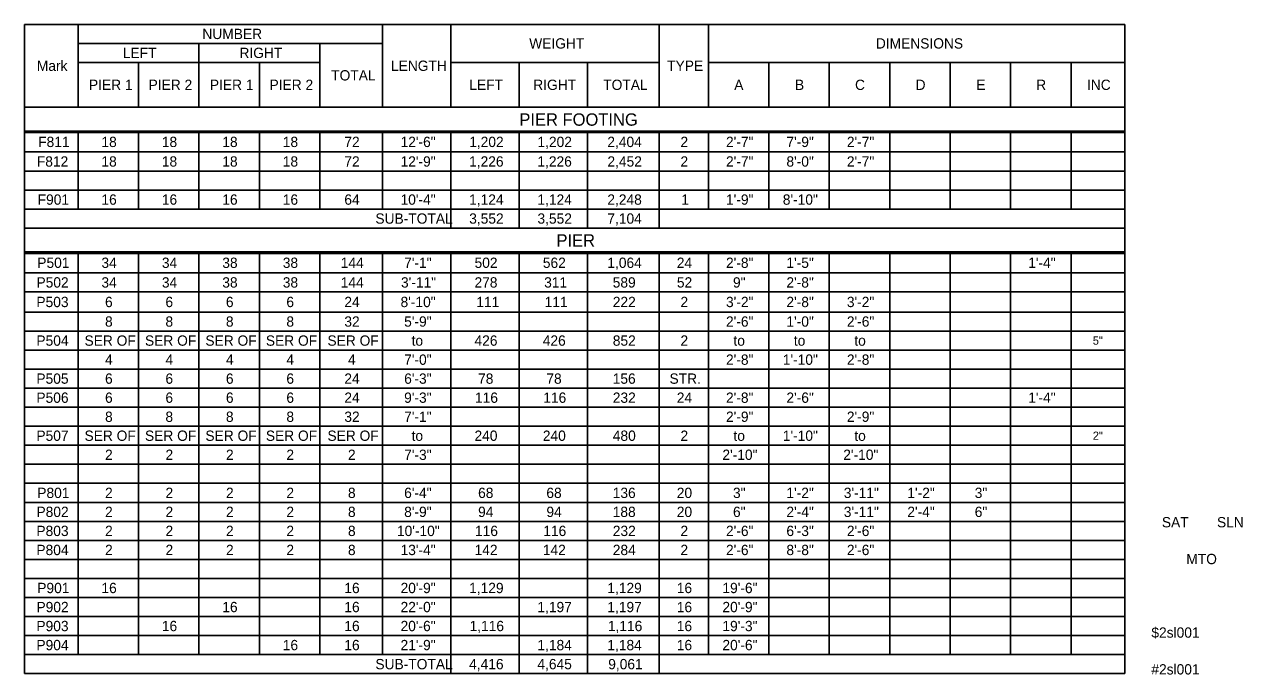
# Model space of a CAD drawing. Extents: x -18.5 to 33.3, y 0.6 to 37.5.
# Drawn here: x 16.73 to 33.29, y 0.6 to 9.44 of the extents above; entities that cross this region are included whole.
import ezdxf

# ---------------------------------------------------------------- set-up
doc = ezdxf.new("R2010")
doc.units = 0
for name, color, linetype in [('BR_X_Beam_Centerline', 7, 'Continuous'), ('BR_X_Beam_Object', 7, 'Continuous'), ('Default', 7, 'Continuous')]:
    doc.layers.add(name, color=color, linetype=linetype)

msp = doc.modelspace()

# ---------------------------------------------------------------- linework, layer by layer
at = {"layer": 'Default'}
for p, q in [((16.731, 9.443), (31.689, 9.443)), ((16.731, 9.443), (16.731, 7.972)), ((17.462, 9.443), (17.462, 8.317)), ((21.601, 9.443), (21.601, 8.317)), ((22.529, 9.443), (22.529, 8.317)), ((25.359, 9.443), (25.359, 8.317)), ((26.029, 9.443), (26.029, 8.317)), ((31.689, 9.443), (31.689, 7.972)), ((17.462, 9.184), (21.601, 9.184)), ((19.105, 9.184), (19.105, 8.317)), ((20.749, 9.184), (20.749, 8.317)), ((17.462, 8.925), (20.749, 8.925)), ((18.283, 8.925), (18.283, 8.317)), ((19.927, 8.925), (19.927, 8.317)), ((22.529, 8.925), (25.359, 8.925)), ((23.457, 8.925), (23.457, 8.317)), ((24.385, 8.925), (24.385, 8.317)), ((26.029, 8.925), (31.689, 8.925)), ((26.85, 8.925), (26.85, 8.317)), ((27.672, 8.925), (27.672, 8.317)), ((28.494, 8.925), (28.494, 8.317)), ((29.316, 8.925), (29.316, 8.317)), ((30.137, 8.925), (30.137, 8.317)), ((30.959, 8.925), (30.959, 8.317)), ((16.731, 8.317), (31.689, 8.317)), ((16.731, 7.992), (31.689, 7.992)), ((16.731, 7.992), (16.731, 6.328)), ((16.731, 7.972), (31.689, 7.972)), ((17.462, 7.972), (17.462, 6.932)), ((18.283, 7.972), (18.283, 6.932)), ((19.105, 7.972), (19.105, 6.932)), ((19.927, 7.972), (19.927, 6.932)), ((20.749, 7.992), (20.749, 6.932)), ((21.601, 7.972), (21.601, 6.932)), ((22.529, 7.972), (22.529, 6.673)), ((23.457, 7.972), (23.457, 6.673)), ((24.385, 7.992), (24.385, 6.673)), ((25.359, 7.972), (25.359, 6.673)), ((26.029, 7.972), (26.029, 6.932)), ((26.85, 7.972), (26.85, 6.932)), ((27.672, 7.972), (27.672, 6.932)), ((28.494, 7.972), (28.494, 6.932)), ((29.316, 7.972), (29.316, 6.932)), ((30.137, 7.972), (30.137, 6.932)), ((30.959, 7.972), (30.959, 6.932)), ((31.689, 7.992), (31.689, 6.328)), ((16.731, 7.708), (31.689, 7.708)), ((16.731, 7.449), (31.689, 7.449)), ((16.731, 7.191), (31.689, 7.191)), ((16.731, 6.932), (31.689, 6.932)), ((16.731, 6.673), (31.689, 6.673)), ((16.731, 6.349), (31.689, 6.349)), ((16.731, 6.349), (16.731, 0.617)), ((16.731, 6.328), (31.689, 6.328)), ((17.462, 6.328), (17.462, 0.876)), ((18.283, 6.328), (18.283, 0.876)), ((19.105, 6.328), (19.105, 0.876)), ((19.927, 6.328), (19.927, 0.876)), ((20.749, 6.349), (20.749, 0.876)), ((21.601, 6.328), (21.601, 0.876)), ((22.529, 6.328), (22.529, 0.617)), ((23.457, 6.328), (23.457, 0.617)), ((24.385, 6.349), (24.385, 0.617)), ((25.359, 6.328), (25.359, 0.617)), ((26.029, 6.328), (26.029, 0.876)), ((26.85, 6.328), (26.85, 0.876)), ((27.672, 6.328), (27.672, 0.876)), ((28.494, 6.328), (28.494, 0.876)), ((29.316, 6.328), (29.316, 0.876)), ((30.137, 6.328), (30.137, 0.876)), ((30.959, 6.328), (30.959, 0.876)), ((31.689, 6.349), (31.689, 0.617)), ((16.731, 6.065), (31.689, 6.065)), ((16.731, 5.806), (31.689, 5.806)), ((16.731, 5.532), (31.689, 5.532)), ((16.731, 5.273), (31.689, 5.273)), ((16.731, 5.015), (31.689, 5.015)), ((16.731, 4.756), (31.689, 4.756)), ((16.731, 4.497), (31.689, 4.497)), ((16.731, 4.239), (31.689, 4.239)), ((16.731, 3.98), (31.689, 3.98)), ((16.731, 3.721), (31.689, 3.721)), ((16.731, 3.462), (31.689, 3.462)), ((16.731, 3.204), (31.689, 3.204)), ((16.731, 2.945), (31.689, 2.945)), ((16.731, 2.686), (31.689, 2.686)), ((16.731, 2.428), (31.689, 2.428)), ((16.731, 2.169), (31.689, 2.169)), ((16.731, 1.91), (31.689, 1.91)), ((16.731, 1.652), (31.689, 1.652)), ((16.731, 1.393), (31.689, 1.393)), ((16.731, 1.134), (31.689, 1.134)), ((16.731, 0.876), (31.689, 0.876)), ((16.731, 0.617), (31.69, 0.617))]:
    msp.add_line(p, q, dxfattribs=at)

# ---------------------------------------------------------------- texts
at = {"layer": 'BR_X_Beam_Centerline'}
for s, height, p in [('NUMBER', 0.14, (19.151, 9.243)), ('LEFT', 0.14, (18.07, 8.985)), ('RIGHT', 0.14, (19.655, 8.985)), ('WEIGHT', 0.14, (23.594, 9.114)), ('DIMENSIONS', 0.14, (28.306, 9.114)), ('Mark', 0.14, (16.901, 8.81)), ('LENGTH', 0.14, (21.715, 8.81)), ('TYPE', 0.14, (25.469, 8.81)), ('TOTAL', 0.14, (20.902, 8.68)), ('PIER 1', 0.14, (17.61, 8.551)), ('PIER 2', 0.14, (18.42, 8.551)), ('PIER 1', 0.14, (19.253, 8.551)), ('PIER 2', 0.14, (20.064, 8.551)), ('LEFT', 0.14, (22.78, 8.551)), ('RIGHT', 0.14, (23.649, 8.551)), ('TOTAL', 0.14, (24.6, 8.551)), ('A', 0.14, (26.381, 8.551)), ('B', 0.14, (27.207, 8.551)), ('C', 0.14, (28.023, 8.551)), ('D', 0.14, (28.846, 8.551)), ('E', 0.14, (29.672, 8.551)), ('R', 0.14, (30.486, 8.551)), ('INC', 0.14, (31.176, 8.551)), ('PIER FOOTING', 0.16799, (23.46, 8.065)), ('F811', 0.14, (16.919, 7.775)), ('18', 0.14, (17.779, 7.775)), ('18', 0.14, (18.6, 7.775)), ('18', 0.14, (19.422, 7.775)), ('18', 0.14, (20.244, 7.775)), ('72', 0.14, (21.081, 7.775)), ('12\'-6"', 0.14, (21.845, 7.775)), ('1,202', 0.14, (22.778, 7.775)), ('1,202', 0.14, (23.706, 7.775)), ('2,404', 0.14, (24.656, 7.775)), ('2', 0.14, (25.65, 7.775)), ('2\'-7"', 0.14, (26.269, 7.775)), ('7\'-9"', 0.14, (27.09, 7.775)), ('2\'-7"', 0.14, (27.912, 7.775)), ('F812', 0.14, (16.901, 7.509)), ('18', 0.14, (17.779, 7.509)), ('18', 0.14, (18.6, 7.509)), ('18', 0.14, (19.422, 7.509)), ('18', 0.14, (20.244, 7.509)), ('72', 0.14, (21.081, 7.509)), ('12\'-9"', 0.14, (21.845, 7.509)), ('1,226', 0.14, (22.777, 7.509)), ('1,226', 0.14, (23.705, 7.509)), ('2,452', 0.14, (24.657, 7.509)), ('2', 0.14, (25.65, 7.509)), ('2\'-7"', 0.14, (26.269, 7.509)), ('8\'-0"', 0.14, (27.09, 7.509)), ('2\'-7"', 0.14, (27.912, 7.509)), ('F901', 0.14, (16.912, 6.991)), ('16', 0.14, (17.779, 6.991)), ('16', 0.14, (18.6, 6.991)), ('16', 0.14, (19.422, 6.991)), ('16', 0.14, (20.244, 6.991)), ('64', 0.14, (21.081, 6.991)), ('10\'-4"', 0.14, (21.845, 6.991)), ('1,124', 0.14, (22.777, 6.991)), ('1,124', 0.14, (23.705, 6.991)), ('2,248', 0.14, (24.656, 6.991)), ('1', 0.14, (25.661, 6.991)), ('1\'-9"', 0.14, (26.269, 6.991)), ('8\'-10"', 0.14, (27.041, 6.991)), ('SUB-TOTAL', 0.14, (21.503, 6.733)), ('3,552', 0.14, (22.778, 6.733)), ('3,552', 0.14, (23.706, 6.733)), ('7,104', 0.14, (24.656, 6.733)), ('PIER', 0.168, (23.964, 6.422)), ('P501', 0.14, (16.907, 6.132)), ('34', 0.14, (17.779, 6.132)), ('34', 0.14, (18.601, 6.132)), ('38', 0.14, (19.422, 6.132)), ('38', 0.14, (20.244, 6.132)), ('144', 0.14, (21.032, 6.132)), ('7\'-1"', 0.14, (21.894, 6.132)), ('502', 0.14, (22.851, 6.132)), ('562', 0.14, (23.779, 6.132)), ('1,064', 0.14, (24.656, 6.132)), ('24', 0.14, (25.6, 6.132)), ('2\'-8"', 0.14, (26.269, 6.132)), ('1\'-5"', 0.14, (27.09, 6.132)), ('1\'-4"', 0.14, (30.377, 6.132)), ('P502', 0.14, (16.896, 5.865)), ('34', 0.14, (17.779, 5.865)), ('34', 0.14, (18.601, 5.865)), ('38', 0.14, (19.422, 5.865)), ('38', 0.14, (20.244, 5.865)), ('144', 0.14, (21.032, 5.865)), ('3\'-11"', 0.14, (21.851, 5.865)), ('278', 0.14, (22.85, 5.865)), ('311', 0.14, (23.797, 5.865)), ('589', 0.14, (24.729, 5.865)), ('52', 0.14, (25.601, 5.865)), ('9"', 0.14, (26.364, 5.865)), ('2\'-8"', 0.14, (27.09, 5.865)), ('P503', 0.14, (16.895, 5.599)), ('6', 0.14, (17.828, 5.599)), ('6', 0.14, (18.649, 5.599)), ('6', 0.14, (19.471, 5.599)), ('6', 0.14, (20.293, 5.599)), ('24', 0.14, (21.081, 5.599)), ('8\'-10"', 0.14, (21.845, 5.599)), ('111', 0.14, (22.875, 5.599)), ('111', 0.14, (23.804, 5.599)), ('222', 0.14, (24.73, 5.599)), ('2', 0.14, (25.65, 5.599)), ('3\'-2"', 0.14, (26.269, 5.599)), ('2\'-8"', 0.14, (27.09, 5.599)), ('3\'-2"', 0.14, (27.912, 5.599)), ('8', 0.14, (17.828, 5.333)), ('8', 0.14, (18.649, 5.333)), ('8', 0.14, (19.471, 5.333)), ('8', 0.14, (20.293, 5.333)), ('32', 0.14, (21.081, 5.333)), ('5\'-9"', 0.14, (21.894, 5.333)), ('2\'-6"', 0.14, (26.269, 5.333)), ('1\'-0"', 0.14, (27.09, 5.333)), ('2\'-6"', 0.14, (27.912, 5.333)), ('P504', 0.14, (16.895, 5.074)), ('SER OF', 0.14, (17.549, 5.074)), ('SER OF', 0.14, (18.371, 5.074)), ('SER OF', 0.14, (19.192, 5.074)), ('SER OF', 0.14, (20.014, 5.074)), ('SER OF', 0.14, (20.851, 5.074)), ('to', 0.14, (21.995, 5.074)), ('426', 0.14, (22.85, 5.074)), ('426', 0.14, (23.778, 5.074)), ('852', 0.14, (24.73, 5.074)), ('2', 0.14, (25.65, 5.074)), ('to', 0.14, (26.37, 5.074)), ('to', 0.14, (27.191, 5.074)), ('to', 0.14, (28.013, 5.074)), ('5"', 0.112, (31.255, 5.088)), ('4', 0.14, (17.828, 4.815)), ('4', 0.14, (18.65, 4.815)), ('4', 0.14, (19.471, 4.815)), ('4', 0.14, (20.293, 4.815)), ('4', 0.14, (21.13, 4.815)), ('7\'-0"', 0.14, (21.894, 4.815)), ('2\'-8"', 0.14, (26.269, 4.815)), ('1\'-10"', 0.14, (27.041, 4.815)), ('2\'-8"', 0.14, (27.912, 4.815)), ('P505', 0.14, (16.895, 4.557)), ('6', 0.14, (17.828, 4.557)), ('6', 0.14, (18.649, 4.557)), ('6', 0.14, (19.471, 4.557)), ('6', 0.14, (20.293, 4.557)), ('24', 0.14, (21.081, 4.557)), ('6\'-3"', 0.14, (21.894, 4.557)), ('78', 0.14, (22.899, 4.557)), ('78', 0.14, (23.827, 4.557)), ('156', 0.14, (24.729, 4.557)), ('STR.', 0.14, (25.501, 4.557)), ('P506', 0.14, (16.895, 4.298)), ('6', 0.14, (17.828, 4.298)), ('6', 0.14, (18.649, 4.298)), ('6', 0.14, (19.471, 4.298)), ('6', 0.14, (20.293, 4.298)), ('24', 0.14, (21.081, 4.298)), ('9\'-3"', 0.14, (21.894, 4.298)), ('116', 0.14, (22.857, 4.298)), ('116', 0.14, (23.785, 4.298)), ('232', 0.14, (24.73, 4.298)), ('24', 0.14, (25.6, 4.298)), ('2\'-8"', 0.14, (26.269, 4.298)), ('2\'-6"', 0.14, (27.09, 4.298)), ('1\'-4"', 0.14, (30.377, 4.298)), ('8', 0.14, (17.828, 4.039)), ('8', 0.14, (18.649, 4.039)), ('8', 0.14, (19.471, 4.039)), ('8', 0.14, (20.293, 4.039)), ('32', 0.14, (21.081, 4.039)), ('7\'-1"', 0.14, (21.894, 4.039)), ('2\'-9"', 0.14, (26.269, 4.039)), ('2\'-9"', 0.14, (27.912, 4.039)), ('P507', 0.14, (16.895, 3.781)), ('SER OF', 0.14, (17.549, 3.781)), ('SER OF', 0.14, (18.371, 3.781)), ('SER OF', 0.14, (19.192, 3.781)), ('SER OF', 0.14, (20.014, 3.781)), ('SER OF', 0.14, (20.851, 3.781)), ('to', 0.14, (21.995, 3.781)), ('240', 0.14, (22.85, 3.781)), ('240', 0.14, (23.779, 3.781)), ('480', 0.14, (24.73, 3.781)), ('2', 0.14, (25.65, 3.781)), ('to', 0.14, (26.37, 3.781)), ('1\'-10"', 0.14, (27.041, 3.781)), ('to', 0.14, (28.013, 3.781)), ('2"', 0.112, (31.255, 3.795)), ('2', 0.14, (17.828, 3.522)), ('2', 0.14, (18.65, 3.522)), ('2', 0.14, (19.472, 3.522)), ('2', 0.14, (20.293, 3.522)), ('2', 0.14, (21.13, 3.522)), ('7\'-3"', 0.14, (21.894, 3.522)), ('2\'-10"', 0.14, (26.22, 3.522)), ('2\'-10"', 0.14, (27.863, 3.522)), ('P801', 0.14, (16.907, 3.004)), ('2', 0.14, (17.828, 3.004)), ('2', 0.14, (18.65, 3.004)), ('2', 0.14, (19.472, 3.004)), ('2', 0.14, (20.293, 3.004)), ('8', 0.14, (21.13, 3.004)), ('6\'-4"', 0.14, (21.894, 3.004)), ('68', 0.14, (22.899, 3.004)), ('68', 0.14, (23.827, 3.004)), ('136', 0.14, (24.729, 3.004)), ('20', 0.14, (25.6, 3.004)), ('3"', 0.14, (26.364, 3.004)), ('1\'-2"', 0.14, (27.09, 3.004)), ('3\'-11"', 0.14, (27.87, 3.004)), ('1\'-2"', 0.14, (28.734, 3.004)), ('3"', 0.14, (29.65, 3.004)), ('P802', 0.14, (16.896, 2.746)), ('2', 0.14, (17.828, 2.746)), ('2', 0.14, (18.65, 2.746)), ('2', 0.14, (19.472, 2.746)), ('2', 0.14, (20.293, 2.746)), ('8', 0.14, (21.13, 2.746)), ('8\'-9"', 0.14, (21.894, 2.746)), ('94', 0.14, (22.899, 2.746)), ('94', 0.14, (23.828, 2.746)), ('188', 0.14, (24.729, 2.746)), ('20', 0.14, (25.6, 2.746)), ('6"', 0.14, (26.364, 2.746)), ('2\'-4"', 0.14, (27.09, 2.746)), ('3\'-11"', 0.14, (27.87, 2.746)), ('2\'-4"', 0.14, (28.734, 2.746)), ('6"', 0.14, (29.65, 2.746)), ('P803', 0.14, (16.895, 2.487)), ('2', 0.14, (17.828, 2.487)), ('2', 0.14, (18.65, 2.487)), ('2', 0.14, (19.472, 2.487)), ('2', 0.14, (20.293, 2.487)), ('8', 0.14, (21.13, 2.487)), ('10\'-10"', 0.14, (21.796, 2.487)), ('116', 0.14, (22.857, 2.487)), ('116', 0.14, (23.785, 2.487)), ('232', 0.14, (24.73, 2.487)), ('2', 0.14, (25.65, 2.487)), ('2\'-6"', 0.14, (26.269, 2.487)), ('6\'-3"', 0.14, (27.09, 2.487)), ('2\'-6"', 0.14, (27.912, 2.487)), ('P804', 0.14, (16.895, 2.228)), ('2', 0.14, (17.828, 2.228)), ('2', 0.14, (18.65, 2.228)), ('2', 0.14, (19.472, 2.228)), ('2', 0.14, (20.293, 2.228)), ('8', 0.14, (21.13, 2.228)), ('13\'-4"', 0.14, (21.845, 2.228)), ('142', 0.14, (22.851, 2.228)), ('142', 0.14, (23.779, 2.228)), ('284', 0.14, (24.73, 2.228)), ('2', 0.14, (25.65, 2.228)), ('2\'-6"', 0.14, (26.269, 2.228)), ('8\'-8"', 0.14, (27.09, 2.228)), ('2\'-6"', 0.14, (27.912, 2.228)), ('P901', 0.14, (16.907, 1.711)), ('16', 0.14, (17.779, 1.711)), ('16', 0.14, (21.081, 1.711)), ('20\'-9"', 0.14, (21.845, 1.711)), ('1,129', 0.14, (22.777, 1.711)), ('1,129', 0.14, (24.656, 1.711)), ('16', 0.14, (25.6, 1.711)), ('19\'-6"', 0.14, (26.22, 1.711)), ('P902', 0.14, (16.896, 1.452)), ('16', 0.14, (19.422, 1.452)), ('16', 0.14, (21.081, 1.452)), ('22\'-0"', 0.14, (21.845, 1.452)), ('1,197', 0.14, (23.705, 1.452)), ('1,197', 0.14, (24.656, 1.452)), ('16', 0.14, (25.6, 1.452)), ('20\'-9"', 0.14, (26.22, 1.452)), ('P903', 0.14, (16.895, 1.194)), ('16', 0.14, (18.6, 1.194)), ('16', 0.14, (21.081, 1.194)), ('20\'-6"', 0.14, (21.845, 1.194)), ('1,116', 0.14, (22.783, 1.194)), ('1,116', 0.14, (24.663, 1.194)), ('16', 0.14, (25.6, 1.194)), ('19\'-3"', 0.14, (26.22, 1.194)), ('P904', 0.14, (16.895, 0.935)), ('16', 0.14, (20.244, 0.935)), ('16', 0.14, (21.081, 0.935)), ('21\'-9"', 0.14, (21.845, 0.935)), ('1,184', 0.14, (23.705, 0.935)), ('1,184', 0.14, (24.656, 0.935)), ('16', 0.14, (25.6, 0.935)), ('20\'-6"', 0.14, (26.22, 0.935)), ('SUB-TOTAL', 0.14, (21.503, 0.676)), ('4,416', 0.14, (22.777, 0.676)), ('4,645', 0.14, (23.705, 0.676)), ('9,061', 0.14, (24.668, 0.676))]:
    msp.add_text(s, height=height, dxfattribs=at).set_placement(p)
at = {"layer": 'BR_X_Beam_Object'}
for s, p in [('SAT', (32.194, 2.605)), ('SLN', (32.943, 2.605)), ('MTO', (32.526, 2.105)), ('$2sl001', (32.051, 1.105)), ('#2sl001', (32.051, 0.605))]:
    msp.add_text(s, height=0.14, dxfattribs=at).set_placement(p)

doc.saveas('drawing.dxf')
